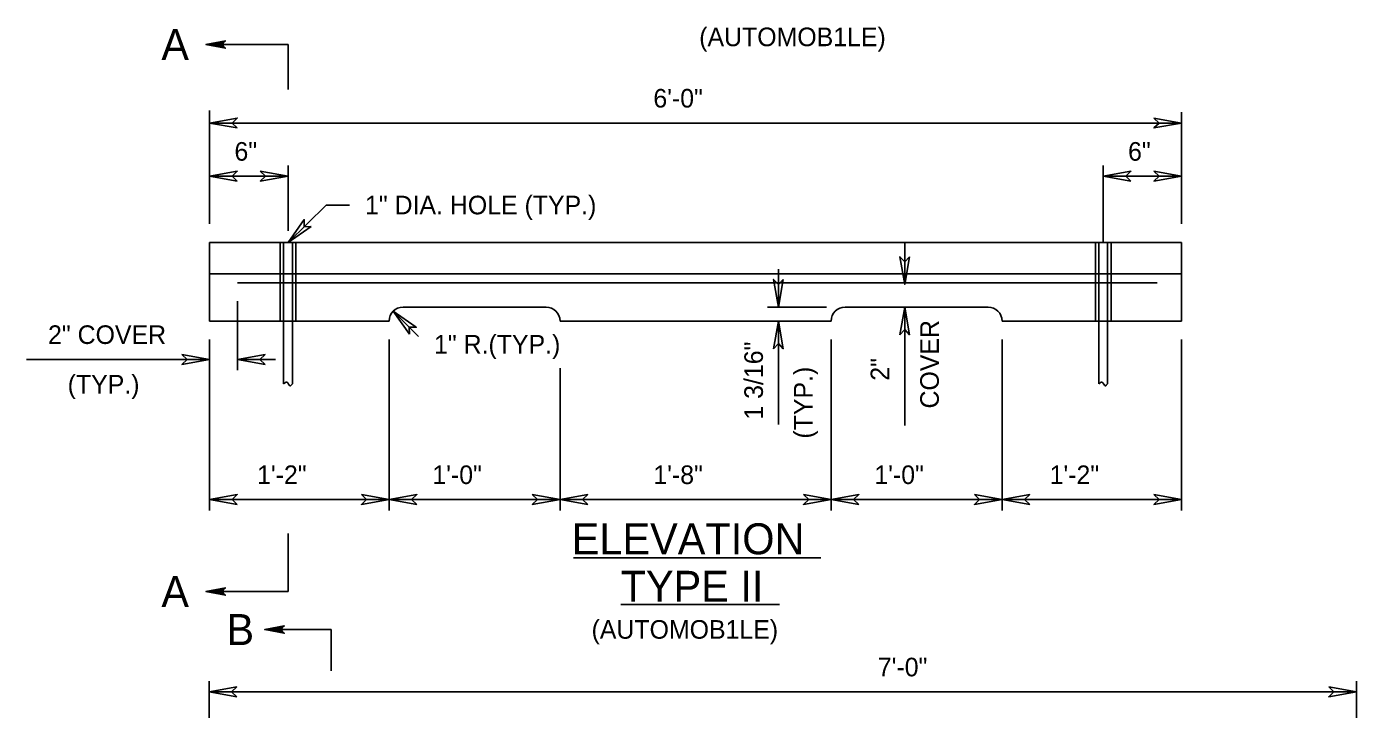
# Model space of a CAD drawing. Extents: x 12.4 to 19.6, y 6 to 16.2.
# Drawn here: x 12.377 to 16.667, y 11.724 to 13.927 of the extents above; entities that cross this region are included whole.
import ezdxf

# ---------------------------------------------------------------- set-up
doc = ezdxf.new("R2010")
doc.units = 0
for name, color, linetype in [('DETL-DIMS', 7, 'Continuous'), ('DETL-LINE', 7, 'Continuous'), ('DETL-NOTE', 7, 'Continuous'), ('DETL-TITL', 7, 'Continuous')]:
    doc.layers.add(name, color=color, linetype=linetype)

msp = doc.modelspace()

# ---------------------------------------------------------------- linework, layer by layer
at = {"layer": 'DETL-DIMS'}
for p, q in [((13.2203, 13.869), (12.9555, 13.869)), ((13.2203, 13.869), (13.2203, 13.7245)), ((12.9672, 13.2903), (12.9672, 13.656)), ((16.103, 13.2903), (16.103, 13.651)), ((12.9672, 13.616), (13.0565, 13.6318)), ((12.9672, 13.616), (16.103, 13.616)), ((12.9672, 13.616), (13.0565, 13.6003)), ((13.0397, 13.616), (13.0565, 13.6318)), ((13.0565, 13.6003), (13.0397, 13.616)), ((16.103, 13.616), (16.0137, 13.6318)), ((16.0137, 13.6318), (16.0305, 13.616)), ((16.103, 13.616), (16.0137, 13.6003)), ((16.0305, 13.616), (16.0137, 13.6003)), ((13.2203, 13.2684), (13.2203, 13.4795)), ((15.8499, 13.2303), (15.8499, 13.4795)), ((12.9672, 13.4445), (13.0565, 13.4603)), ((13.2203, 13.4445), (12.9672, 13.4445)), ((12.9672, 13.4445), (13.0565, 13.4288)), ((13.0397, 13.4445), (13.0565, 13.4603)), ((13.0565, 13.4288), (13.0397, 13.4445)), ((13.2203, 13.4445), (13.1309, 13.4603)), ((13.1309, 13.4603), (13.1478, 13.4445)), ((13.2203, 13.4445), (13.1309, 13.4288)), ((13.1478, 13.4445), (13.1309, 13.4288)), ((15.8499, 13.4445), (15.9393, 13.4603)), ((15.8499, 13.4445), (16.103, 13.4445)), ((15.8499, 13.4445), (15.9393, 13.4288)), ((15.9224, 13.4445), (15.9393, 13.4603)), ((15.9393, 13.4288), (15.9224, 13.4445)), ((16.103, 13.4445), (16.0137, 13.4603)), ((16.0137, 13.4603), (16.0305, 13.4445)), ((16.103, 13.4445), (16.0137, 13.4288)), ((16.0305, 13.4445), (16.0137, 13.4288)), ((13.2203, 13.2303), (13.343, 13.3515)), ((13.343, 13.3515), (13.4187, 13.3515)), ((13.2203, 13.2303), (13.2728, 13.3043)), ((13.2719, 13.2813), (13.2728, 13.3043)), ((13.2203, 13.2303), (13.2949, 13.2819)), ((13.2949, 13.2819), (13.2719, 13.2813)), ((15.2097, 13.23), (15.2097, 13.0953)), ((15.2097, 13.0953), (15.1939, 13.1847)), ((15.2097, 13.1678), (15.1939, 13.1847)), ((15.2097, 13.0953), (15.2254, 13.1847)), ((15.2254, 13.1847), (15.2097, 13.1678)), ((14.8023, 13.1443), (14.8023, 13.0222)), ((14.8023, 13.0222), (14.7865, 13.1115)), ((14.8023, 13.0947), (14.7865, 13.1115)), ((14.8023, 13.0222), (14.818, 13.1115)), ((14.818, 13.1115), (14.8023, 13.0947)), ((13.0572, 13.0409), (13.0572, 12.8183)), ((13.5597, 13.009), (13.6413, 12.9274)), ((13.5597, 13.009), (13.6117, 12.9347)), ((13.5597, 13.009), (13.634, 12.957)), ((14.9574, 13.0222), (14.7673, 13.0222)), ((15.2097, 13.0222), (15.1939, 12.9328)), ((15.2097, 13.0222), (15.2097, 12.6399)), ((15.2097, 13.0222), (15.2254, 12.9328)), ((13.6117, 12.9347), (13.6109, 12.9578)), ((13.6109, 12.9578), (13.634, 12.957)), ((14.8023, 12.9772), (14.7865, 12.8878)), ((14.8023, 12.9772), (14.8023, 12.644)), ((14.8023, 12.9772), (14.818, 12.8878)), ((12.9672, 12.9172), (12.9672, 12.3664)), ((13.5465, 12.3664), (13.5465, 12.9172)), ((14.9724, 12.3664), (14.9724, 12.9173)), ((15.1939, 12.9328), (15.2097, 12.9497)), ((15.2097, 12.9497), (15.2254, 12.9328)), ((15.5237, 12.3664), (15.5237, 12.9173)), ((16.103, 12.3664), (16.103, 12.9173)), ((14.7865, 12.8878), (14.8023, 12.9047)), ((14.8023, 12.9047), (14.818, 12.8878)), ((12.9672, 12.8533), (12.377, 12.8533)), ((12.9672, 12.8533), (12.8778, 12.869)), ((12.8778, 12.869), (12.8947, 12.8533)), ((12.9672, 12.8533), (12.8778, 12.8375)), ((12.8947, 12.8533), (12.8778, 12.8375)), ((13.0572, 12.8533), (13.1465, 12.869)), ((13.18, 12.8533), (13.0572, 12.8533)), ((13.0572, 12.8533), (13.1465, 12.8375)), ((13.1297, 12.8533), (13.1465, 12.869)), ((13.1465, 12.8375), (13.1297, 12.8533)), ((14.0978, 12.3664), (14.0978, 12.8254)), ((12.9672, 12.4014), (13.0565, 12.4172)), ((12.9672, 12.4014), (13.5465, 12.4014)), ((12.9672, 12.4014), (13.0565, 12.3857)), ((13.0397, 12.4014), (13.0565, 12.4172)), ((13.0565, 12.3857), (13.0397, 12.4014)), ((13.5465, 12.4014), (13.4572, 12.4172)), ((13.4572, 12.4172), (13.474, 12.4014)), ((13.5465, 12.4014), (13.4572, 12.3857)), ((13.474, 12.4014), (13.4572, 12.3857)), ((13.5465, 12.4014), (13.6359, 12.4172)), ((13.5465, 12.4014), (14.0978, 12.4014)), ((13.5465, 12.4014), (13.6359, 12.3857)), ((13.619, 12.4014), (13.6359, 12.4172)), ((13.6359, 12.3857), (13.619, 12.4014)), ((14.0978, 12.4014), (14.0084, 12.4172)), ((14.0084, 12.4172), (14.0253, 12.4014)), ((14.0978, 12.4014), (14.0084, 12.3857)), ((14.0253, 12.4014), (14.0084, 12.3857)), ((14.0978, 12.4014), (14.1872, 12.4172)), ((14.0978, 12.4014), (14.9724, 12.4014)), ((14.0978, 12.4014), (14.1872, 12.3857)), ((14.1703, 12.4014), (14.1872, 12.4172)), ((14.1872, 12.3857), (14.1703, 12.4014)), ((14.9724, 12.4014), (14.883, 12.4172)), ((14.883, 12.4172), (14.8999, 12.4014)), ((14.9724, 12.4014), (14.883, 12.3857)), ((14.8999, 12.4014), (14.883, 12.3857)), ((14.9724, 12.4014), (15.0618, 12.4172)), ((14.9724, 12.4014), (15.5237, 12.4014)), ((14.9724, 12.4014), (15.0618, 12.3857)), ((15.0449, 12.4014), (15.0618, 12.4172)), ((15.0618, 12.3857), (15.0449, 12.4014)), ((15.5237, 12.4014), (15.4343, 12.4172)), ((15.4343, 12.4172), (15.4512, 12.4014)), ((15.5237, 12.4014), (15.4343, 12.3857)), ((15.4512, 12.4014), (15.4343, 12.3857)), ((15.5237, 12.4014), (15.613, 12.4172)), ((15.5237, 12.4014), (16.103, 12.4014)), ((15.5237, 12.4014), (15.613, 12.3857)), ((15.5962, 12.4014), (15.613, 12.4172)), ((15.613, 12.3857), (15.5962, 12.4014)), ((16.103, 12.4014), (16.0137, 12.4172)), ((16.0137, 12.4172), (16.0305, 12.4014)), ((16.103, 12.4014), (16.0137, 12.3857)), ((16.0305, 12.4014), (16.0137, 12.3857)), ((13.2203, 12.1044), (13.2203, 12.2918)), ((13.2203, 12.1044), (12.9555, 12.1044)), ((13.3592, 11.9819), (13.1452, 11.9819)), ((13.3592, 11.9819), (13.3592, 11.8485)), ((12.9654, 11.4321), (12.9654, 11.816)), ((12.9654, 11.781), (13.0548, 11.7967)), ((13.0379, 11.781), (13.0548, 11.7967)), ((16.6667, 11.781), (16.5773, 11.7967)), ((16.5773, 11.7967), (16.5942, 11.781)), ((16.6667, 11.4321), (16.6667, 11.816)), ((12.9654, 11.781), (16.6667, 11.781)), ((12.9654, 11.781), (13.0548, 11.7652)), ((13.0548, 11.7652), (13.0379, 11.781)), ((16.6667, 11.781), (16.5773, 11.7652)), ((16.5942, 11.781), (16.5773, 11.7652))]:
    msp.add_line(p, q, dxfattribs=at)
for points in [[(12.9555, 13.869), (13.0184, 13.8808), (13.0135, 13.8774), (13.011, 13.8732), (13.0104, 13.869), (13.011, 13.8648), (13.0135, 13.8605), (13.0184, 13.8572), (12.9555, 13.869), (13.0135, 13.8605), (13.011, 13.8648), (12.9555, 13.869), (13.0104, 13.869), (13.011, 13.8732), (12.9555, 13.869), (13.0135, 13.8774)], [(12.9555, 12.1044), (13.0184, 12.1162), (13.0135, 12.1128), (13.011, 12.1087), (13.0104, 12.1044), (13.011, 12.1002), (13.0135, 12.0959), (13.0184, 12.0925), (12.9555, 12.1044), (13.0135, 12.0959), (13.011, 12.1002), (12.9555, 12.1044), (13.0104, 12.1044), (13.011, 12.1087), (12.9555, 12.1044), (13.0135, 12.1128)], [(13.1452, 11.9819), (13.208, 11.9937), (13.2033, 11.9904), (13.2008, 11.9862), (13.2, 11.9819), (13.2008, 11.9777), (13.2033, 11.9736), (13.208, 11.9702), (13.1452, 11.9819), (13.2033, 11.9736), (13.2008, 11.9777), (13.1452, 11.9819), (13.2, 11.9819), (13.2008, 11.9862), (13.1452, 11.9819), (13.2033, 11.9904)]]:
    msp.add_lwpolyline(points, dxfattribs=at)
for points in [[(13.0565, 13.6003), (12.9672, 13.616), (13.0565, 13.6318), (13.0397, 13.616)], [(16.0137, 13.6318), (16.103, 13.616), (16.0137, 13.6003), (16.0305, 13.616)], [(13.0565, 13.4288), (12.9672, 13.4445), (13.0565, 13.4603), (13.0397, 13.4445)], [(13.1309, 13.4603), (13.2203, 13.4445), (13.1309, 13.4288), (13.1478, 13.4445)], [(15.9393, 13.4288), (15.8499, 13.4445), (15.9393, 13.4603), (15.9224, 13.4445)], [(16.0137, 13.4603), (16.103, 13.4445), (16.0137, 13.4288), (16.0305, 13.4445)], [(13.2949, 13.2819), (13.2203, 13.2303), (13.2728, 13.3043), (13.2719, 13.2813)], [(15.2254, 13.1847), (15.2097, 13.0953), (15.1939, 13.1847), (15.2097, 13.1678)], [(14.818, 13.1115), (14.8023, 13.0222), (14.7865, 13.1115), (14.8023, 13.0947)], [(13.6117, 12.9347), (13.5597, 13.009), (13.634, 12.957), (13.6109, 12.9578)], [(15.1939, 12.9328), (15.2097, 13.0222), (15.2254, 12.9328), (15.2097, 12.9497)], [(14.7865, 12.8878), (14.8023, 12.9772), (14.818, 12.8878), (14.8023, 12.9047)], [(12.8778, 12.869), (12.9672, 12.8533), (12.8778, 12.8375), (12.8947, 12.8533)], [(13.1465, 12.8375), (13.0572, 12.8533), (13.1465, 12.869), (13.1297, 12.8533)], [(13.0565, 12.3857), (12.9672, 12.4014), (13.0565, 12.4172), (13.0397, 12.4014)], [(13.4572, 12.4172), (13.5465, 12.4014), (13.4572, 12.3857), (13.474, 12.4014)], [(13.6359, 12.3857), (13.5465, 12.4014), (13.6359, 12.4172), (13.619, 12.4014)], [(14.0084, 12.4172), (14.0978, 12.4014), (14.0084, 12.3857), (14.0253, 12.4014)], [(14.1872, 12.3857), (14.0978, 12.4014), (14.1872, 12.4172), (14.1703, 12.4014)], [(14.883, 12.4172), (14.9724, 12.4014), (14.883, 12.3857), (14.8999, 12.4014)], [(15.0618, 12.3857), (14.9724, 12.4014), (15.0618, 12.4172), (15.0449, 12.4014)], [(15.4343, 12.4172), (15.5237, 12.4014), (15.4343, 12.3857), (15.4512, 12.4014)], [(15.613, 12.3857), (15.5237, 12.4014), (15.613, 12.4172), (15.5962, 12.4014)], [(16.0137, 12.4172), (16.103, 12.4014), (16.0137, 12.3857), (16.0305, 12.4014)], [(13.0548, 11.7652), (12.9654, 11.781), (13.0548, 11.7967), (13.0379, 11.781)], [(16.5773, 11.7967), (16.6667, 11.781), (16.5773, 11.7652), (16.5942, 11.781)]]:
    msp.add_lwpolyline(points, close=True, dxfattribs=at)
at = {"layer": 'DETL-LINE'}
for p, q in [((12.9672, 13.2303), (12.9672, 12.9772)), ((12.9672, 13.2303), (13.1949, 13.2303)), ((13.1949, 13.2303), (13.1949, 12.9772)), ((13.1949, 13.2303), (13.2455, 13.2303)), ((13.2062, 13.2303), (13.2062, 12.9772)), ((13.2343, 13.2303), (13.2343, 12.9772)), ((13.2455, 13.2303), (13.2455, 12.9772)), ((13.2455, 13.2303), (16.103, 13.2303)), ((15.8247, 13.2303), (15.8247, 12.9772)), ((15.8359, 13.2303), (15.8359, 12.9772)), ((15.864, 13.2303), (15.864, 12.9772)), ((15.8753, 13.2303), (15.8753, 12.9772)), ((16.103, 13.2303), (16.103, 12.9772)), ((12.9672, 13.129), (14.7763, 13.129)), ((14.7763, 13.129), (15.1735, 13.129)), ((15.1735, 13.129), (16.103, 13.129)), ((13.0572, 13.1009), (14.775, 13.1009)), ((14.775, 13.1009), (16.0243, 13.1009)), ((13.5915, 13.0222), (14.0528, 13.0222)), ((15.0174, 13.0222), (15.4787, 13.0222)), ((12.9672, 12.9772), (13.5465, 12.9772)), ((13.2062, 12.9772), (13.2062, 12.7747)), ((13.2343, 12.9772), (13.2343, 12.7747)), ((14.0978, 12.9772), (14.9724, 12.9772)), ((15.5237, 12.9772), (16.103, 12.9772)), ((15.8359, 12.9772), (15.8359, 12.7747)), ((15.864, 12.9772), (15.864, 12.7747))]:
    msp.add_line(p, q, dxfattribs=at)
for centre, start, end in [((13.5915, 12.9773), 90, 180), ((14.0527, 12.9773), 0, 90), ((15.0174, 12.9773), 90, 180), ((15.4787, 12.9773), 0, 90)]:
    msp.add_arc(centre, 0.045, start, end, dxfattribs=at)
for points in [[(13.2062, 12.7747), (13.2167, 12.78), (13.2264, 12.7682), (13.2343, 12.7747)], [(15.8359, 12.7747), (15.8464, 12.78), (15.8562, 12.7682), (15.864, 12.7747)]]:
    msp.add_spline(points, degree=3, dxfattribs=at)
at = {"layer": 'DETL-TITL'}
for p, q in [((14.1413, 12.2136), (14.9394, 12.2136)), ((14.2944, 12.0624), (14.8062, 12.0624))]:
    msp.add_line(p, q, dxfattribs=at)

# ---------------------------------------------------------------- texts
at = {"layer": 'DETL-NOTE'}
for s, height, p in [('A', 0.1, (12.8116, 13.819)), ('(AUTOMOB1LE)', 0.06, (14.5467, 13.8639)), ('6\'-0"', 0.06, (14.3988, 13.666)), ('6"', 0.06, (13.0475, 13.4945)), ('6"', 0.06, (15.9301, 13.4945)), ('1" DIA. HOLE (TYP.)', 0.06, (13.4687, 13.3215)), ('2" COVER', 0.06, (12.4462, 12.9033)), ('1" R.(TYP.)', 0.06, (13.6913, 12.8724)), ('(TYP.)', 0.06, (12.5095, 12.7433)), ('1\'-2"', 0.06, (13.1205, 12.4514)), ('1\'-0"', 0.06, (13.6859, 12.4514)), ('1\'-8"', 0.06, (14.3988, 12.4514)), ('1\'-0"', 0.06, (15.1117, 12.4514)), ('1\'-2"', 0.06, (15.6771, 12.4514)), ('A', 0.1, (12.8116, 12.0544)), ('B', 0.1, (13.0217, 11.9319)), ('(AUTOMOB1LE)', 0.06, (14.1994, 11.9524)), ('7\'-0"', 0.06, (15.123, 11.831))]:
    msp.add_text(s, height=height, dxfattribs=at).set_placement(p)
for s, p in [('COVER', (15.3197, 12.6951)), ('1 3/16"', (14.7523, 12.6593)), ('2"', (15.1597, 12.7847)), ('(TYP.)', (14.9123, 12.598))]:
    msp.add_text(s, height=0.06, rotation=90, dxfattribs=at).set_placement(p)
at = {"layer": 'DETL-TITL'}
for s, p in [('ELEVATION', (14.1356, 12.2247)), ('TYPE II', (14.2931, 12.0714))]:
    msp.add_text(s, height=0.1, dxfattribs=at).set_placement(p)

doc.saveas('drawing.dxf')
